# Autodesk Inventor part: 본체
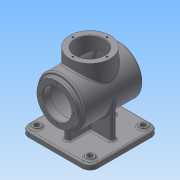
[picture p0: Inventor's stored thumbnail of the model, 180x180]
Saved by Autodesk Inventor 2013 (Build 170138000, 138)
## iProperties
Created: 2015-07
Part Number: 본체
Material: 일반
Document SubType Name: Modeling
Designer: Administrator
Density: 1 g/cm^3
Author: Administrator
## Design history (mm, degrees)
sketch "스케치1"
  geometry: C1 r 45 at (0, 0); 1 further point
  constraints: 1 centre point, 1 coincident
  dimensions: "d0" = 90 diameter of C1
extrude "돌출1" new body sketch "스케치1" stored distance "d1" = 110; taper "d2" = 0 deg
sketch "스케치4"
  geometry: L1 (40, 48)-(40, -48); L2 (40, -48)-(0, -48); L3 (0, 48)-(40, 48); L4 (45, -55)-(-45, -55) reference; L5 (-45, -55)-(-45, 55) reference; L6 (-45, 55)-(45, 55) reference; L7 (45, 55)-(45, -55) reference; L8 (0, 48)-(0, -48); 1 further point
  constraints: 8 end point, 4 parallel, 1 perpendicular, 1 vertical
  dimensions: "d10" = 5 distance between parallel lines of L7 L1; "d11" = 7 distance between parallel lines of L3 L6; "d12" = 7 distance between parallel lines of L4 L2; "d14" = 40 distance between parallel lines of L1 L8
revolve "회전1" sketch "스케치4" stored, may be unused: angle "d15" = 90 deg
sketch "스케치5"
  geometry: C1 r 45 at (0, 0) reference; C2 r 38 at (0, 0)
  constraints: 1 centre point, 1 coincident
  dimensions: "d16" = 76 diameter of C2
extrude "돌출3" join sketch "스케치5" distance "d17" = 7; taper "d18" = 0 deg
sketch "스케치6"
  geometry: C1 r 38 at (0, 0) reference; C2 r 27 at (0, 0)
  constraints: 1 centre point, 1 coincident
  dimensions: "d19" = 54 diameter of C2
extrude "돌출4" cut sketch "스케치6" distance "d20" = 14; taper "d21" = 0 deg
node "작업 평면1"
sketch "스케치7"
  geometry: L1 (-65, 65)-(65, 65); L2 (65, 65)-(65, -65); L3 (65, -65)-(-65, -65); L4 (-65, -65)-(-65, 65); L5 (-65, 65)-(65, -65); L6 (65, 65)-(-65, -65); 1 further point
  constraints: 12 end point, 2 midpoint, 2 parallel, 1 horizontal, 1 perpendicular
  dimensions: "d23" = 130 distance of L2.end L3.end; "d24" = 130 distance of L1.end L2.end
extrude "돌출5" join sketch "스케치7" distance "d25" = 10; taper "d26" = 0 deg
sketch "스케치8"
  geometry: L1 (-65, 65)-(-65, -65) reference; L2 (-5, 45)-(-5, 5); L3 (-5, 5)-(-5, 45); L4 (-5, 45)-(5, 45); L5 (5, 45)-(5, 5); L6 (5, 5)-(45, 5); L7 (45, 5)-(45, -5); L8 (45, -5)-(5, -5); L9 (5, -5)-(5, -45); L10 (5, -45)-(-5, -45); L11 (-5, -45)-(-5, -5); L12 (-5, -5)-(-45, -5); L13 (-45, -5)-(-45, 5); L14 (-45, 5)-(-5, 5); 3 further points
  constraints: 26 end point, 9 parallel, 7 collinear, 2 midpoint, 2 perpendicular, 1 horizontal alignment, 1 vertical alignment
  dimensions: "d27" = 10 distance of L2.start L4.end; "d29" = 10 distance of L12.end L13.end; "d30" = 90 distance between parallel lines of L10 L4; "d31" = 90 distance between parallel lines of L7 L13; "d32" = 10 distance between parallel lines of L9 L11
extrude "돌출6" join sketch "스케치8" stored distance "d33" = 10; taper "d34" = 0 deg
node "작업 평면3"
sketch "스케치9"
  geometry: C1 r 38 at (0, 0); 1 further point
  constraints: 1 centre point, 1 coincident
  dimensions: "d37" = 76 diameter of C1
extrude "돌출7" join sketch "스케치9" stored distance "d38" = 10; taper "d39" = 0 deg
sketch "스케치10"
  geometry: C1 r 38 at (0, 0) reference; C2 r 27 at (0, 0)
  constraints: 1 centre point, 1 coincident
  dimensions: "d40" = 54 diameter of C2
extrude "돌출8" cut sketch "스케치10" distance "d41" = 50; taper "d42" = 0 deg
fillet "모깎기1" dims "d43" = 3
fillet "모깎기2" dims "d44" = 3
fillet "모깎기3" dims "d45" = 15
sketch "스케치11"
  geometry: C1 r 7.5 at (-50, 50); C2 r 7.5 at (-50, -50); A1 r 15 centre (-50, 50) between (-50, 65) and (-65, 50) reference; A2 r 15 centre (-50, -50) between (-65, -50) and (-50, -65) reference; 1 further point
  constraints: 2 centre point, 2 coincident
  dimensions: "d46" = 15 diameter of C1; "d47" = 15 diameter of C2
extrude "돌출9" join sketch "스케치11" distance "d48" = 3; taper "d49" = 0 deg
sketch "스케치12"
  geometry: C1 r 7.5 at (0, 0) reference; C2 r 7.5 at (0, -100) reference; C3 r 5 at (0, 0); C4 r 5 at (0, -100); 1 further point
  constraints: 2 centre point, 2 coincident
  dimensions: "d50" = 10 diameter of C3; "d51" = 10 diameter of C4
extrude "돌출10" cut sketch "스케치12" distance "d52" = 13; taper "d53" = 0 deg
fillet "모깎기5" dims "d55" = 3
sketch "스케치13"
  geometry: C1 r 27 at (0, 0) reference; 1 further point
  constraints: 1 horizontal alignment
  dimensions: "d56" = 32 distance of point (-32, 0) C1.centre
hole "구멍1" sketch "스케치13" at (-32, 0) diameter "d57" = 3.242; stored, may be unused: countersink angle "d61" = 90 deg, drill point angle "d63" = 118 deg; dims "d58" = 8, "d59" = 4, "d60" = 2, "d62" = 10
sketch "스케치14"
  geometry: C1 r 27 at (0, 0) reference; 1 further point
  constraints: 1 vertical alignment
  dimensions: "d67" = 32 distance of C1.centre point (0, 32)
hole "구멍2" sketch "스케치14" at (0, 32) diameter "d68" = 3.242; stored, may be unused: countersink angle "d72" = 90 deg, drill point angle "d74" = 118 deg; dims "d69" = 8, "d70" = 4, "d71" = 2, "d73" = 10
sketch "스케치15"
  geometry: C1 r 42 at (0, 0) reference; 1 further point
  constraints: 1 coincident, 1 other
feature "엠보싱1" sketch "스케치15" dims "d78" = 0.5, "d79" = 0
chamfer "모따기1" distance "d80" = 1; stored, may be unused: second distance "d81" = 2, angle "d82" = 45 deg
node "솔리드1"
mirror "대칭1"
pattern_circular "원형 패턴1" dims angle "d65" = 360 deg
pattern_circular "원형 패턴2" dims angle "d76" = 360 deg
node "투영된 루프2"
node "절단 모서리 투영1"
other parameters: "d22" = -78, "d36" = 62
